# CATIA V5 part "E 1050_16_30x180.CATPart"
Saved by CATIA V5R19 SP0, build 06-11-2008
Nomenclature: E 1050_16_30x180
Description: PART-E 1050_16_30x180-DESC
Property "Hersteller": "Meusburger"
Property "Material": "1.7131 ~ 60 HRC"
Property "Bestellnummer": "E 1050/16/30x180"
Property "Teilenummer": "E 1050/16/30x180"
Property "Beschreibung": "Führungsbolzen für Ausstoßerführung _ Guide bolt for pusher guide"
Material "Steel": density 7860 kg/m3, Young's modulus 2e+11 Pa, Poisson ratio 0.266, thermal expansion 1.17e-05 1/K
Bounding box of the stored display mesh (mm): x -15 to 15, y -15 to 15, z 0 to 180
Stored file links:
  G:\UTB\Kombinované\Bakalářská práce\Catia\FORMA\E 1050_16_30x180.CATPart
  D:\Aplikace\CATIA\Nová složka\win_b64\startup\materials\Catalog.CATMaterial
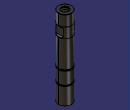
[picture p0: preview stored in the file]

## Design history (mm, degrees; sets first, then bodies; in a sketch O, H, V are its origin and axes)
Body1 "E 1050_16_30x180" (main body)
  Solid1: solid without history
